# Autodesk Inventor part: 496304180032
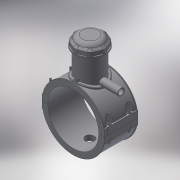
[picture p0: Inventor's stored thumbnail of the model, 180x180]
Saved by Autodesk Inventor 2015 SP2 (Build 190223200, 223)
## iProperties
Created: 2017-07
Part Number: 496304180032
Material: Generic
Description: PLASSON TAPPING SADDLE 180x32
Document SubType Name: Modeling
Designer: KIM
Mass: 1199.5 g
Surface Area: 2505.7 cm^2
Volume: 1199.5 cm^3
Density: 1 g/cm^3
Appearance: Default
Author: KIM
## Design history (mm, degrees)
derived "496304.ipt"
feature "Solid1::496304.ipt"
feature "Solid2::496304.ipt"
feature "Solid4::496304.ipt"
feature "Solid5::496304.ipt"
tag "TaggingFeature1"
body "Solid1"
body "Solid2"
other parameters: "B_" = 219, "L_" = 118, "d_t" = 6, "H_2" = 138, "H_1" = 18, "d_1" = 32, "H_" = 144, "d1" = 205.2, "d148" = 2.7, "d160" = 2.7, "d169" = 3.375, "d192" = 6.3, "d2" = 219, "d3" = 45, "d4" = 118, "d5" = 0, "d6" = 0.1, "d8" = 0, "d19" = 6, "d20" = 6, "d21" = 70.8, "d23" = 0, "d24" = 35.4, "d26" = 0, "d29" = 3, "d31" = 6, "d32" = 0, "d33" = 0, "d34" = 0.6, "d40" = 106.704, "d41" = 72, "d43" = 0, "d45" = 0, "d47" = 173.4, "d70" = 15, "d72" = 0, "d73" = 6, "d75" = 5, "d76" = 0, "d77" = 9, "d79" = 15, "d80" = 47.2, "d82" = 5 deg, "d84" = 4, "d85" = 14, "d86" = 0, "d87" = 3, "d88" = 0, "d89" = 1, "d90" = 1, "d91" = 94.4, "d92" = 0, "d93" = 0.5, "d94" = 94.73684, "d96" = 209.304, "d97" = 2.36, "d98" = 0, "d102" = 1.8, "d120" = 140 deg, "d121" = 24.228, "d122" = 20 deg, "d123" = 410.4, "d124" = 123.12, "d126" = 0, "d143" = 185.4, "d145" = 19.38462, "d149" = 2.7, "d150" = 21.32308, "d153" = 118, "d154" = 0, "d156" = 102.6, "d157" = 160 deg, "d159" = 5.04, "d161" = 2.7, "d162" = 70.8, "d163" = 0, "d167" = 18, "d168" = 100.09756, "d170" = 3.375, "d172" = 0, "d173" = 1, "d176" = 20 deg, "d177" = 12.6, "d178" = 25.2, "d180" = 0, "d183" = 10.08, "d184" = 10.08, "d185" = 38.35, "d186" = 38.35, "d187" = 102.6, "d188" = 7.56, "d189" = 12.6, "d190" = 0, "d191" = 153.9, "d193" = 6.3, "d194" = 4.13, "d195" = 90 deg, "d197" = 0, "d199" = 0, "d200" = 12.6, "d202" = 0, "d203" = 138, "d204" = 68.4, "d205" = 50.4, "d206" = 61.2, "d207" = 103.5, "d208" = 107.64, "d209" = 128.34, "d210" = 61.92, "d211" = 72, "d212" = 57.6, "d213" = 1.8, "d216" = 0, "d217" = 18, "d218" = 18, "d219" = 3.6, "d224" = 0, "d230" = 3.6, "d233" = 6, "d236" = 109.5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
